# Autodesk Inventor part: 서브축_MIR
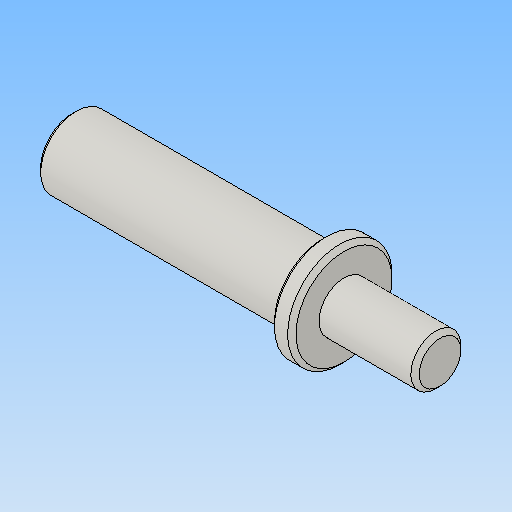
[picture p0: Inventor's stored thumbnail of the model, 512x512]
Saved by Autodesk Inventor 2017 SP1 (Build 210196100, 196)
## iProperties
Created: 2018-09
Part Number: 서브축_MIR
Material: 강철, 연강
Document SubType Name: Modeling
Designer: MRC
Density: 7.86 g/cm^3
Appearance: 강철
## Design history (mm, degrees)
derived "서브축.ipt"
  sketch "스케치1"
    geometry: L1 (18.818, -7)-(18.818, 7) reference; L2 (41.331, -13.5)-(41.331, 13.5) reference; L3 (46.5, 12.249)-(46.5, -12.249) reference; L4 (18.331, 0)-(106.5, 0) reference; L5 (18.331, 0)-(18.331, -6) reference; L6 (18.331, -6)-(41.331, -6) reference; L7 (41.331, -12.5)-(46.5, -12.5) reference; L8 (46.5, -8.5)-(106.5, -8.5) reference; L9 (106.5, -8.5)-(106.5, 0) reference; L10 (46.5, -8.5)-(46.5, -12.5) reference; L11 (41.331, -6)-(41.331, -12.5) reference; 2 further points
  sketch "스케치2"
    geometry: L1 (-11.5, 5)-(-11.5, -5) reference; L2 (5.5, -2)-(-4.5, -2) reference; L3 (-4.5, 2)-(5.5, 2) reference; A1 r 2 centre (-4.5, 0) between (-4.5, 2) and (-4.5, -2) reference; A2 r 2 centre (5.5, 0) between (5.5, -2) and (5.5, 2) reference; 2 further points
  sketch "스케치3"
    geometry: L1 (30, -7.5)-(30, 7.5) reference; L2 (30, 3)-(15, 3) reference; L3 (15, -3)-(30, -3) reference; A1 r 3 centre (15, 0) between (15, 3) and (15, -3) reference; 2 further points
  node "작업 평면1"
  node "작업 평면2"
feature "솔리드1::서브축.ipt"
tag "피쳐 태그1"
node "솔리드1"
